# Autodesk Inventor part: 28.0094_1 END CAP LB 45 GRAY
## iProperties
Created: 2007-01
Part Number: 28.0094_1 END CAP LB 45 GRAY
Document SubType Name: Modeling
Designer: Andy Moles
Material: ABS Plastic
Density: 1.06 g/cm^3
Author: Andy Moles
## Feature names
1. Extrusion1
2. Fillet1
3. Fillet2
4. Extrusion2
